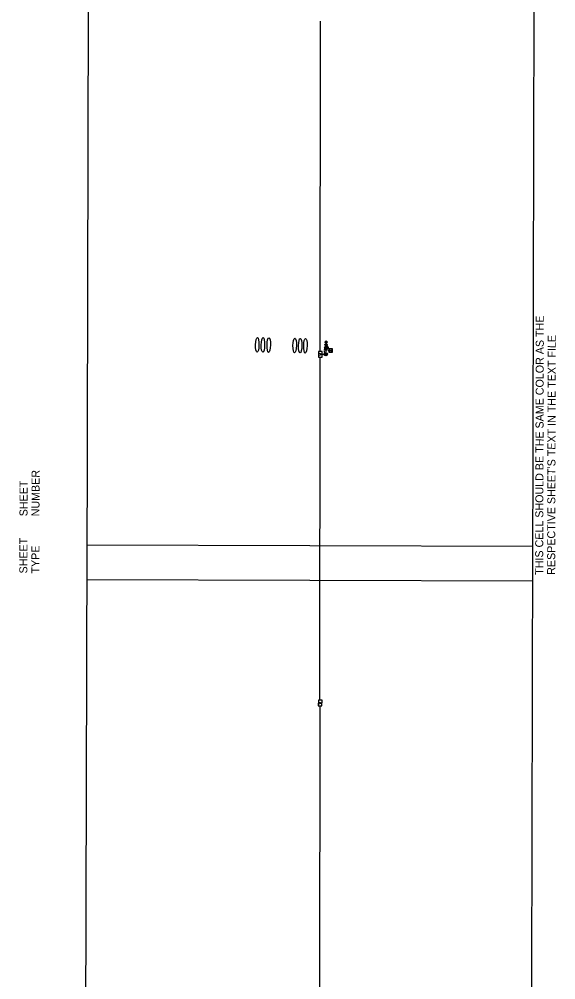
# Model space of a CAD drawing. Extents: x 601462 to 605493, y 331960 to 402715.
# Drawn here: x 602658 to 603831, y 380772 to 382873 of the extents above; entities that cross this region are included whole.
import ezdxf

# ---------------------------------------------------------------- set-up
doc = ezdxf.new("R2010")
doc.units = 0
for name, color, linetype in [('Default', 7, 'Continuous'), ('P_FTMS', 7, 'Continuous'), ('P_FTMSConduit', 7, 'Continuous'), ('P_MISC_TXT_1A (Construction)', 7, 'Continuous'), ('P_MISC_TXT_1B (Construction)', 7, 'Continuous')]:
    doc.layers.add(name, color=color, linetype=linetype)

# ---------------------------------------------------------------- blocks, each defined once
blk = doc.blocks.new('FMB')
at = {"layer": 'P_FTMS'}
for p, q in [((24, -24), (-24, 24)), ((-24, -24), (24, 24))]:
    blk.add_line(p, q, dxfattribs=at)
blk.add_lwpolyline([(24, -24), (24, 24), (-24, 24), (-24, -24)], close=True, dxfattribs=at)
blk = doc.blocks.new('POINT_DISPLAY')
at = {"layer": 'Default'}
blk.add_line((0, 0), (0, 0), dxfattribs=at)
blk = doc.blocks.new('_U229')
at = {"layer": 'P_FTMS'}
for p, q in [((-5, 3), (2, 0)), ((-2, 3), (-4, 0)), ((-2, 3), (-4, 0)), ((-2, 3), (-4, 1)), ((-3, 3), (-4, 1)), ((-3, 3), (-4, 1)), ((-3, 3), (-4, 2)), ((-4, 3), (-4, 2)), ((-4, 3), (-4, 3)), ((-4, 3), (2, 0)), ((-4, 3), (2, 0)), ((-4, 3), (1, 0)), ((-4, 2), (1, -1)), ((-4, 2), (1, -1)), ((-4, 2), (0, -1)), ((-4, 1), (0, -1)), ((-4, 1), (0, -1)), ((-4, 0), (0, -2)), ((1, 3), (-3, -3)), ((0, 3), (-3, -3)), ((0, 3), (-3, -2)), ((0, 3), (-3, -2)), ((-1, 3), (-3, -2)), ((-1, 3), (-3, -1)), ((-1, 3), (-3, -1)), ((-3, 3), (2, 0)), ((1, 3), (-2, -3)), ((1, 3), (-2, -3)), ((-2, 3), (3, 1)), ((2, 3), (-1, -2)), ((2, 3), (-1, -2)), ((-1, 3), (3, 1)), ((2, 3), (0, -1)), ((0, 3), (3, 1)), ((3, 3), (1, -1)), ((1, 3), (4, 1)), ((1, 3), (3, 1)), ((3, 2), (1, 0)), ((2, 3), (4, 2)), ((3, 2), (2, 0)), ((4, 2), (3, 1)), ((4, 2), (3, 1)), ((3, 2), (4, 2)), ((4, 2), (4, 2)), ((4, 2), (4, 2)), ((-4, 0), (-1, -2)), ((-3, 0), (-1, -2)), ((-3, -1), (-1, -2)), ((-3, -1), (-1, -2)), ((-3, -2), (-2, -3)), ((-3, -2), (-2, -3)), ((-3, -3), (-2, -3)), ((-3, -3), (-2, -3)), ((-3, -3), (-3, -3))]:
    blk.add_line(p, q, dxfattribs=at)
blk.add_lwpolyline([(-5, 4), (5, 2), (-3, -4)], close=True, dxfattribs=at)
blk.add_blockref('POINT_DISPLAY', (5, 2), dxfattribs=at)
blk = doc.blocks.new('_U231')
at = {"layer": 'P_FTMS'}
for p, q in [((12.1, 1.6), (-12.2, -0.1)), ((11.8, 3), (-12.1, 1.4)), ((11.9, 2.3), (-12.1, 0.6)), ((12.1, 0.8), (-12.1, -0.8)), ((12.1, 0.1), (-12.1, -1.6)), ((11.6, 3.7), (-12, 2.1)), ((-11.9, 2.5), (-11.4, -4.2)), ((11.3, 4.4), (-11.8, 2.9)), ((11, 5.2), (-11.6, 3.6)), ((10.6, 5.9), (-11.4, 4.4)), ((-11.3, 4.5), (-10.6, -6)), ((10.2, 6.6), (-11, 5.1)), ((9.8, 7.3), (-10.7, 5.9)), ((-10.7, 5.9), (-9.8, -7.2)), ((9.2, 8), (-10.2, 6.6)), ((-10, 6.9), (-9, -8.2)), ((8.6, 8.6), (-9.7, 7.4)), ((-9.3, 7.8), (-8.2, -9)), ((7.8, 9.3), (-9, 8.2)), ((-8.6, 8.5), (-7.4, -9.6)), ((6.9, 10), (-8.2, 9)), ((-8, 9.2), (-6.6, -10.2)), ((-7.3, 9.7), (-5.9, -10.6)), ((5.8, 10.7), (-7.2, 9.8)), ((-6.6, 10.3), (-5.1, -11)), ((4.5, 11.3), (-6, 10.6)), ((-5.9, 10.7), (-4.4, -11.4)), ((-5.1, 11), (-3.6, -11.6)), ((-4.4, 11.3), (-2.9, -11.8)), ((2.5, 11.9), (-4.1, 11.5)), ((-3.7, 11.6), (-2.1, -12)), ((-3, 11.8), (-1.4, -12.1)), ((-2.3, 12), (-0.6, -12.2)), ((-1.6, 12.1), (0.1, -12.2)), ((-0.8, 12.1), (0.8, -12.1)), ((-0.1, 12.2), (1.6, -12.1)), ((0.6, 12.1), (2.3, -11.9)), ((1.4, 12.1), (3, -11.8)), ((2.1, 12), (3.7, -11.6)), ((2.9, 11.8), (4.4, -11.3)), ((3.6, 11.6), (5.1, -11)), ((4.4, 11.3), (5.9, -10.7)), ((5.1, 11), (6.6, -10.2)), ((5.9, 10.6), (7.3, -9.8)), ((6.6, 10.2), (8, -9.2)), ((7.4, 9.7), (8.6, -8.6)), ((8.2, 9), (9.3, -7.8)), ((9, 8.2), (10, -6.9)), ((9.8, 7.2), (10.7, -5.8)), ((10.6, 5.9), (11.3, -4.5)), ((11.5, 4), (11.9, -2.5)), ((12.1, -0.6), (-12, -2.3)), ((12.1, -1.4), (-11.8, -3)), ((12, -2.1), (-11.6, -3.7)), ((11.8, -2.9), (-11.3, -4.4)), ((11.6, -3.6), (-11, -5.1)), ((11.3, -4.4), (-10.7, -5.9)), ((11.1, -5.1), (-10.2, -6.6)), ((10.6, -5.9), (-9.8, -7.3)), ((10.2, -6.6), (-9.2, -8)), ((9.6, -7.4), (-8.5, -8.6)), ((9, -8.2), (-7.8, -9.3)), ((8.2, -9), (-6.9, -10)), ((7.3, -9.8), (-5.8, -10.7)), ((6, -10.6), (-4.5, -11.3)), ((4.1, -11.5), (-2.6, -11.9))]:
    blk.add_line(p, q, dxfattribs=at)
blk.add_circle((0, 0), 12.2, dxfattribs=at)
blk = doc.blocks.new('FMD')
at = {"layer": 'P_FTMS'}
for p, q in [((17, 18), (-17, 18)), ((-16, 16), (-16, 18)), ((16, 16), (-16, 16)), ((-15, 15), (-15, 20)), ((15, 19), (-15, 19)), ((15, 15), (-15, 15)), ((14, 20), (-14, 20)), ((13, 22), (-13, 22)), ((-13, 13), (-13, 21)), ((13, 13), (-13, 13)), ((-12, 12), (-12, 23)), ((12, 12), (-12, 12)), ((11, 23), (-11, 23)), ((10, 25), (-10, 25)), ((-10, 10), (-10, 24)), ((10, 10), (-10, 10)), ((-9, 9), (-9, 26)), ((9, 9), (-9, 9)), ((8, 26), (-8, 26)), ((7, 28), (-7, 28)), ((-7, 7), (-7, 27)), ((7, 7), (-7, 7)), ((-6, 6), (-6, 29)), ((6, 6), (-6, 6)), ((5, 29), (-5, 29)), ((4, 31), (-4, 31)), ((-4, 4), (-4, 30)), ((4, 4), (-4, 4)), ((-3, 3), (-3, 32)), ((3, 3), (-3, 3)), ((2, 32), (-2, 32)), ((1, 34), (-1, 34)), ((-1, 1), (-1, 33)), ((1, 1), (-1, 1)), ((0, 0), (0, 34)), ((1, 1), (1, 33)), ((3, 3), (3, 32)), ((4, 4), (4, 30)), ((6, 6), (6, 29)), ((7, 7), (7, 27)), ((9, 9), (9, 26)), ((10, 10), (10, 24)), ((12, 12), (12, 23)), ((13, 13), (13, 21)), ((15, 15), (15, 20)), ((16, 16), (16, 18))]:
    blk.add_line(p, q, dxfattribs=at)
blk.add_lwpolyline([(-17, 17), (0, 34), (17, 17), (0, 0)], close=True, dxfattribs=at)
blk = doc.blocks.new('FTMS_FCV')
at = {"layer": 'P_FTMS'}
blk.add_line((13, 16), (1, -22), dxfattribs=at)
blk.add_lwpolyline([(39, 24), (-39, 24), (-39, -24), (39, -24)], close=True, dxfattribs=at)
blk.add_lwpolyline([(-12, 16), (1, -22)], dxfattribs=at)

msp = doc.modelspace()

# ---------------------------------------------------------------- linework, layer by layer
at = {"layer": 'P_FTMS'}
msp.add_circle((603327.9, 382139.9), 3.75, dxfattribs=at)
for centre, start, end in [((603327.5, 382135.4), 32.6299, 138.8855), ((603328.2, 382144.4), 212.6299, 318.8855)]:
    msp.add_arc(centre, 3.75, start, end, dxfattribs=at)
for centre in [(603178.1, 382160.4), (603190.5, 382160.2), (603203.3, 382160), (603260, 382158.8), (603272, 382158.6), (603283.4, 382158.4)]:
    msp.add_ellipse(centre, major_axis=(0.3, 16), ratio=0.23471, dxfattribs=at)
at = {"layer": 'P_FTMSConduit'}
for p, q in [((603334.7, 382148.1), (603332.6, 382147.5)), ((603319.5, 382139.7), (603324.3, 382139.8))]:
    msp.add_line(p, q, dxfattribs=at)
for points in [[(603315.6, 382146.2), (603316.2, 382868.5)], [(603325, 382149.2), (603325.6, 382151.9)], [(603325.5, 382142.6), (603325, 382144.8)], [(603315, 381383.5), (603315.7, 382133.3)], [(603313.8, 379885.4), (603313.9, 380091.4), (603315.5, 381370.6)]]:
    msp.add_lwpolyline(points, dxfattribs=at)
msp.add_arc((603334.7, 382147.1), 10, 167.5397, 192.8998, dxfattribs=at)
at = {"layer": 'P_MISC_TXT_1A (Construction)'}
msp.add_lwpolyline([(603780.4, 381644.6), (603784.5, 383219.6), (602809.5, 383222.1), (602805.4, 381647.1)], close=True, dxfattribs=at)
msp.add_lwpolyline([(603780.4, 381644.6), (603784.5, 383219.6), (602809.5, 383222.1), (602805.4, 381647.1)], close=True, dxfattribs=at)
at = {"layer": 'P_MISC_TXT_1B (Construction)'}
msp.add_lwpolyline([(603776.6, 380144.6), (603780.6, 381719.6), (602805.6, 381722.1), (602801.6, 380147.1)], close=True, dxfattribs=at)
msp.add_lwpolyline([(603776.6, 380144.6), (603780.6, 381719.6), (602805.6, 381722.1), (602801.6, 380147.1)], close=True, dxfattribs=at)

# ---------------------------------------------------------------- block references
at = {"layer": 'P_FTMS'}
for name, p, xscale, yscale, rotation in [('FMD', (603326, 382166.4), 0.1640416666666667, 0.16404166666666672, -91.54665377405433), ('FTMS_FCV', (603315.9, 382139.7), 0.16404166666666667, 0.16404166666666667, 88.76248754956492), ('_U231', (603329.1, 382153.9), 0.32808333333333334, 0.32808333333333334, 2.5604819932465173), ('FMD', (603325.9, 382160.8), 0.1640416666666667, 0.16404166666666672, -91.54665377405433), ('_U229', (603328.8, 382147.5), 0.19685000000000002, 0.19685000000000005, 19.6160567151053), ('FMB', (603338.7, 382148.1), 0.1640416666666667, 0.16404166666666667, 89.4786762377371), ('FTMS_FCV', (603315.7, 381377.1), 0.16404166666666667, 0.16404166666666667, 88.76248754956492)]:
    msp.add_blockref(name, p, dxfattribs=dict(at, xscale=xscale, yscale=yscale, rotation=rotation))

# ---------------------------------------------------------------- texts
at = {"layer": 'P_MISC_TXT_1A (Construction)'}
for s, p in [('THIS CELL SHOULD BE THE SAME COLOR AS THE', (603803.1, 381657.5)), ('THIS CELL SHOULD BE THE SAME COLOR AS THE', (603803.1, 381657.5)), ("RESPECTIVE SHEET'S TEXT IN THE TEXT FILE", (603829.3, 381657.4)), ("RESPECTIVE SHEET'S TEXT IN THE TEXT FILE", (603829.3, 381657.4)), ('NUMBER', (602702.1, 381785.3)), ('NUMBER', (602702.1, 381785.3)), ('SHEET', (602675.9, 381785.4)), ('SHEET', (602675.9, 381785.4)), ('SHEET', (602675.6, 381660.4)), ('SHEET', (602675.6, 381660.4)), ('TYPE', (602701.8, 381660.3)), ('TYPE', (602701.8, 381660.3))]:
    msp.add_text(s, height=17.5, rotation=89.8526, dxfattribs=at).set_placement(p)

doc.saveas('drawing.dxf')
